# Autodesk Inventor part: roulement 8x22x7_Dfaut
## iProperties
Created: 2006-03
Part Number: roulement 8x22x7_Dfaut
Document SubType Name: Modeling
Designer: Flavien MARTY
Author: Flavien MARTY
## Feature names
1. Base1
